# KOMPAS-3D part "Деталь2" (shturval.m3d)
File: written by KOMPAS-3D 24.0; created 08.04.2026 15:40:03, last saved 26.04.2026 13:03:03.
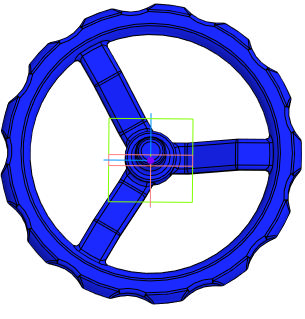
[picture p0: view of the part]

Document properties: Автор: R2D2; Полное имя файла: C:\Работа\VSO2130M-F-S Клапан запорный DN.ru\DN50\DN50\shturval.m3d

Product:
- Body: Твердое тело1  | qty 1
    Масса: 1.255283
- Part/product: Деталь2
    Масса: 1.255283
    additional columns: Типовые

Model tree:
1. Твердое тело1  (labels: Твердое тело1)
2. Масштабирование:1
3. Масштабирование : Твердое тело1
     Масштаб по оси Х = 1; Масштаб по оси Y = 1; Масштаб по оси Z = 1; Коэффициент = 1.219

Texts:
  Масштабирование : Вершина.Начало координат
